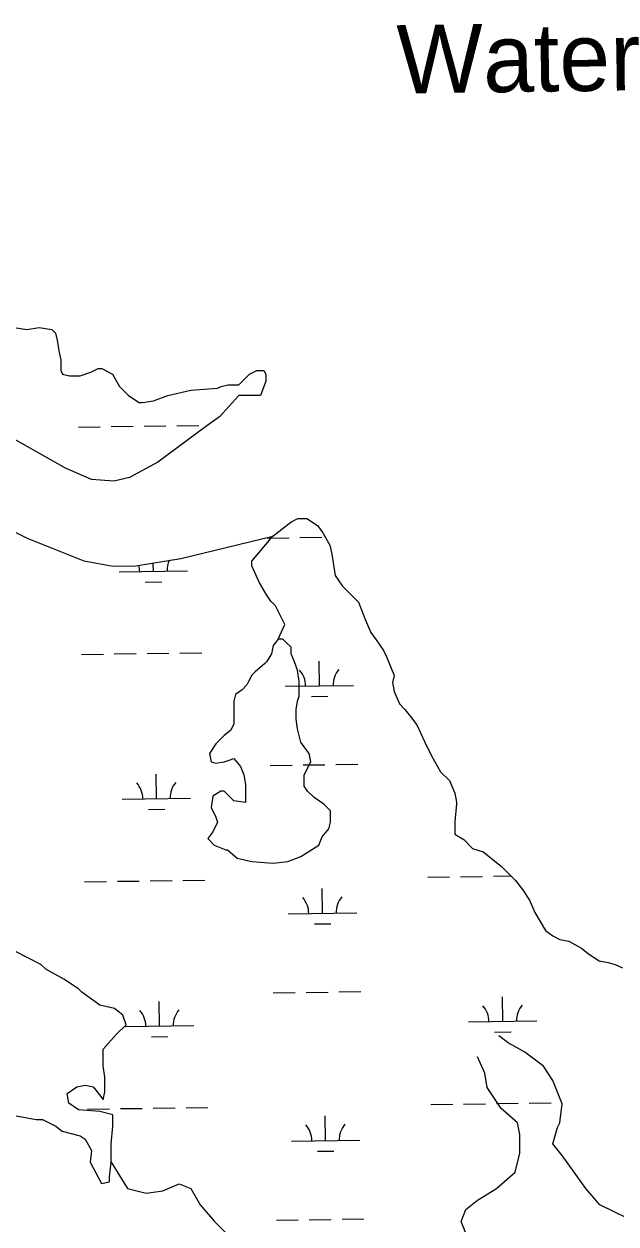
# Model space of a CAD drawing. Extents: x 3753511 to 3791668, y 379550 to 405377.
# Drawn here: x 3781759 to 3782625, y 401064 to 402820 of the extents above; entities that cross this region are included whole.
import ezdxf

# ---------------------------------------------------------------- set-up
doc = ezdxf.new("R2010")
doc.units = 0
for name, color, linetype in [('V-RIVR-IDEN', 7, 'Continuous'), ('V-TOPO-SHOR', 7, 'Continuous'), ('V-WETL-SWMP', 7, 'Continuous')]:
    doc.layers.add(name, color=color, linetype=linetype)

msp = doc.modelspace()

# ---------------------------------------------------------------- linework, layer by layer
at = {"layer": 'V-TOPO-SHOR'}
for p, q in [((3782172.8, 402096.5), (3782188.4, 402086)), ((3782188.4, 402086), (3782196.2, 402075.6)), ((3782196.2, 402075.6), (3782206.7, 402057.3)), ((3782206.7, 402057.3), (3782209.3, 402044.3)), ((3782209.3, 402044.3), (3782214.5, 402013)), ((3782214.5, 402013), (3782224.9, 401997.3)), ((3782224.9, 401997.3), (3782248.4, 401973.8)), ((3782248.4, 401973.8), (3782258.8, 401947.7)), ((3782258.8, 401947.7), (3782266.7, 401929.4)), ((3782266.7, 401929.4), (3782274.5, 401919)), ((3782274.5, 401919), (3782284.9, 401903.4)), ((3782284.9, 401903.4), (3782290.1, 401892.9)), ((3782290.1, 401892.9), (3782300.6, 401866.8)), ((3782300.6, 401866.8), (3782298, 401856.4)), ((3782298, 401856.4), (3782300.6, 401843.3)), ((3782300.6, 401843.3), (3782308.4, 401825.1)), ((3782308.4, 401825.1), (3782316.2, 401817.2)), ((3782316.2, 401817.2), (3782326.6, 401804.2)), ((3782326.6, 401804.2), (3782334.5, 401793.8)), ((3782334.5, 401793.8), (3782344.9, 401770.3)), ((3782344.9, 401770.3), (3782355.3, 401749.4)), ((3782355.3, 401749.4), (3782368.4, 401725.9)), ((3782368.4, 401725.9), (3782381.4, 401712.9)), ((3782381.4, 401712.9), (3782389.2, 401694.6)), ((3782389.2, 401694.6), (3782391.8, 401681.5)), ((3782391.8, 401678.9), (3782389.2, 401652.8)), ((3782391.8, 401681.5), (3782391.8, 401678.9)), ((3782389.2, 401652.8), (3782389.2, 401634.6)), ((3782389.2, 401634.6), (3782402.3, 401626.7)), ((3782402.3, 401626.7), (3782415.3, 401613.7)), ((3782415.3, 401613.7), (3782431, 401608.5)), ((3782431, 401608.5), (3782457, 401587.6)), ((3782457, 401587.6), (3782477.9, 401566.7)), ((3782477.9, 401566.7), (3782488.3, 401553.7)), ((3782488.3, 401553.7), (3782498.8, 401538)), ((3782498.8, 401538), (3782506.6, 401519.8)), ((3782506.6, 401519.8), (3782522.2, 401493.7)), ((3782522.2, 401493.7), (3782532.7, 401485.8)), ((3782532.7, 401485.8), (3782543.1, 401480.6)), ((3782543.1, 401480.6), (3782556.1, 401478)), ((3782556.1, 401478), (3782574.4, 401467.6)), ((3782574.4, 401467.6), (3782584.8, 401459.7)), ((3782584.8, 401459.7), (3782600.5, 401449.3)), ((3782600.5, 401449.3), (3782613.5, 401446.7)), ((3782613.5, 401446.7), (3782623.9, 401444.1)), ((3782623.9, 401444.1), (3782634.4, 401438.9))]:
    msp.add_line(p, q, dxfattribs=at)
for points in [[(3781745.1, 402375.7), (3781763.3, 402373.1), (3781781.6, 402375.7), (3781799.8, 402373.1), (3781805.1, 402367.8), (3781807.7, 402357.4), (3781810.3, 402341.7), (3781812.9, 402328.7), (3781812.9, 402313), (3781815.5, 402307.8), (3781825.9, 402305.2), (3781841.6, 402305.2), (3781857.2, 402310.4), (3781867.6, 402315.7), (3781872.9, 402315.7), (3781888.5, 402307.8), (3781898.9, 402289.6), (3781912, 402276.5), (3781927.6, 402266.1), (3781932.8, 402266.1), (3781948.5, 402268.7), (3781969.4, 402276.5), (3782003.3, 402284.3), (3782042.4, 402286.9), (3782047.6, 402289.6), (3782058, 402292.2), (3782073.7, 402292.2), (3782089.3, 402307.8), (3782099.7, 402313), (3782110.2, 402313), (3782112.8, 402307.8), (3782112.8, 402297.4), (3782105, 402276.5)], [(3782130.8, 401920), (3782140.9, 401941.3), (3782127.1, 401968.8), (3782120.2, 401975.6), (3782113.4, 401985.9), (3782103, 402003.1), (3782092.7, 402027.2), (3782092.7, 402034.1), (3782123.2, 402070.4)], [(3781726.7, 401226.5), (3781776.9, 401217), (3781786.5, 401217), (3781805.6, 401207.4), (3781815.2, 401200.2), (3781841.5, 401193.1), (3781848.7, 401188.3), (3781858.2, 401171.6), (3781855.8, 401154.8), (3781872.6, 401123.7), (3781884.5, 401126.1), (3781884.5, 401133.3), (3781886.9, 401154.8), (3781886.9, 401181.1), (3781889.3, 401207.4), (3781889.3, 401224.2), (3781870.2, 401228.9), (3781839.1, 401231.3), (3781824.8, 401240.9), (3781822.4, 401255.2), (3781836.7, 401264.8), (3781848.7, 401267.2), (3781860.6, 401264.8), (3781870.2, 401252.9), (3781875, 401245.7), (3781877.4, 401257.6), (3781877.4, 401279.2), (3781875, 401295.9), (3781875, 401319.8), (3781894.1, 401341.3), (3781908.5, 401355.7), (3781903.7, 401370), (3781891.7, 401379.6), (3781870.2, 401384.4), (3781843.9, 401403.5), (3781839.1, 401408.3), (3781817.6, 401422.6), (3781791.3, 401437), (3781784.1, 401444.1), (3781745.9, 401463.3)], [(3782642.5, 401072.4), (3782601.5, 401092.1), (3782580.9, 401116.2), (3782563.7, 401140.3), (3782546.5, 401164.3), (3782532.8, 401181.5), (3782539.6, 401205.6), (3782543.1, 401212.5), (3782546.5, 401240), (3782532.8, 401274.3), (3782519, 401295), (3782491.5, 401315.6), (3782467.4, 401329.3), (3782453.7, 401339.7)], [(3782488.7, 400934.2), (3782477.8, 400961.5), (3782477.8, 400968.4), (3782488.1, 400982.1), (3782488.1, 400989), (3782460.6, 400995.9), (3782450.2, 400995.9), (3782436.5, 401006.2), (3782422.7, 401023.4), (3782415.9, 401040.6), (3782405.6, 401050.9), (3782398.7, 401068.1), (3782405.6, 401085.3), (3782422.7, 401099), (3782450.2, 401116.2), (3782477.8, 401140.3), (3782484.6, 401167.8), (3782484.6, 401195.3), (3782481.2, 401212.5), (3782457.1, 401233.1), (3782436.5, 401264), (3782433.1, 401284.7), (3782422.7, 401308.7)], [(3781886.9, 401154.8), (3781910.5, 401116.2), (3781938, 401109.3), (3781962.1, 401112.8), (3781986.2, 401123.1), (3782003.3, 401116.2), (3782017.1, 401092.1), (3782037.7, 401068.1), (3782068.7, 401037.1), (3782085.8, 401033.7), (3782096.2, 401030.3), (3782113.4, 401030.3), (3782137.4, 401023.4), (3782171.8, 401016.5), (3782189, 401019.9), (3782199.3, 401009.6), (3782206.2, 400999.3), (3782213, 400978.7), (3782216.5, 400958.1), (3782226.8, 400937.4), (3782230.2, 400927.1), (3782233.3, 400917.2)]]:
    msp.add_lwpolyline(points, dxfattribs=at)
msp.add_lwpolyline([(3782150, 401898.5), (3782150, 401908), (3782142.8, 401915.2), (3782138, 401920), (3782130.8, 401920), (3782123.7, 401910.4), (3782121.3, 401898.5), (3782114.1, 401886.5), (3782111.7, 401884.1), (3782097.4, 401872.2), (3782092.6, 401867.4), (3782087.8, 401857.8), (3782085.4, 401853), (3782078.2, 401845.9), (3782068.7, 401838.7), (3782066.3, 401829.1), (3782066.3, 401812.4), (3782066.3, 401795.6), (3782061.5, 401786.1), (3782051.9, 401778.9), (3782040, 401766.9), (3782030.4, 401752.6), (3782032.8, 401740.6), (3782040, 401738.3), (3782051.9, 401740.6), (3782059.1, 401743), (3782066.3, 401745.4), (3782075.8, 401733.5), (3782080.6, 401721.5), (3782083, 401707.2), (3782083, 401688), (3782083, 401680.9), (3782066.3, 401683.3), (3782063.9, 401685.6), (3782051.9, 401697.6), (3782047.1, 401697.6), (3782035.2, 401690.4), (3782032.8, 401673.7), (3782040, 401659.3), (3782042.4, 401652.2), (3782035.2, 401637.8), (3782028, 401628.3), (3782037.6, 401618.7), (3782054.3, 401611.5), (3782056.7, 401611.5), (3782071, 401599.6), (3782092.6, 401594.8), (3782123.7, 401592.4), (3782145.2, 401594.8), (3782164.3, 401602), (3782190.6, 401618.7), (3782195.4, 401630.7), (3782205, 401642.6), (3782207.3, 401652.2), (3782207.3, 401668.9), (3782197.8, 401678.5), (3782183.4, 401688), (3782173.9, 401697.6), (3782169.1, 401704.8), (3782169.1, 401721.5), (3782178.6, 401740.6), (3782176.3, 401752.6), (3782169.1, 401762.2), (3782164.3, 401769.3), (3782159.5, 401788.5), (3782157.1, 401802.8), (3782157.1, 401817.2), (3782159.5, 401829.1), (3782161.9, 401836.3), (3782161.9, 401845.9), (3782161.9, 401857.8), (3782159.5, 401874.5), (3782154.7, 401886.5)], close=True, dxfattribs=at)
at = {"layer": 'V-WETL-SWMP'}
for p, q in [((3781838.8, 402230.2), (3781870.8, 402230.7)), ((3781886.8, 402230.9), (3781918.8, 402231.3)), ((3781934.8, 402231.5), (3781966.8, 402232)), ((3781982.8, 402232.2), (3782014.8, 402232.6)), ((3781656.2, 402121.2), (3781764, 402067.6)), ((3782123.2, 402070.4), (3782149.3, 402091.2)), ((3782149.3, 402091.2), (3782159.7, 402096.5)), ((3782159.7, 402096.5), (3782172.8, 402096.5)), ((3782172.8, 402096.5), (3782188.4, 402086)), ((3782188.4, 402086), (3782196.2, 402075.6)), ((3782196.2, 402075.6), (3782206.7, 402057.3)), ((3781764, 402067.6), (3781846.8, 402034.4)), ((3781988.7, 402038.1), (3782123.2, 402070.4)), ((3782114.9, 402067.8), (3782146.9, 402068.2)), ((3782162.9, 402068.4), (3782194.9, 402068.9)), ((3782206.7, 402057.3), (3782209.3, 402044.3)), ((3781922.7, 402027), (3781988.7, 402038.1)), ((3782209.3, 402044.3), (3782214.5, 402013)), ((3781846.8, 402034.4), (3781889.6, 402026.8)), ((3781889.6, 402026.8), (3781922.7, 402027)), ((3781898.5, 402018.4), (3781998.5, 402019.8)), ((3781948.5, 402019.1), (3781948.4, 402031.3)), ((3781936.7, 402003.5), (3781960.7, 402003.8)), ((3782214.5, 402013), (3782224.9, 401997.3)), ((3782224.9, 401997.3), (3782248.4, 401973.8)), ((3782248.4, 401973.8), (3782258.8, 401947.7)), ((3782258.8, 401947.7), (3782266.7, 401929.4)), ((3782266.7, 401929.4), (3782274.5, 401919)), ((3782274.5, 401919), (3782284.9, 401903.4)), ((3781843.3, 401897.6), (3781875.3, 401898)), ((3781891.3, 401898.2), (3781923.3, 401898.7)), ((3781939.3, 401898.9), (3781971.3, 401899.3)), ((3781987.3, 401899.5), (3782019.3, 401900)), ((3782284.9, 401903.4), (3782290.1, 401892.9)), ((3782191.3, 401851.6), (3782190.8, 401887.6)), ((3782290.1, 401892.9), (3782300.6, 401866.8)), ((3782300.6, 401866.8), (3782298, 401856.4)), ((3782141.3, 401850.9), (3782241.3, 401852.2)), ((3782298, 401856.4), (3782300.6, 401843.3)), ((3782300.6, 401843.3), (3782308.4, 401825.1)), ((3782179.5, 401836), (3782203.5, 401836.3)), ((3782308.4, 401825.1), (3782316.2, 401817.2)), ((3782316.2, 401817.2), (3782326.6, 401804.2)), ((3782326.6, 401804.2), (3782334.5, 401793.8)), ((3782334.5, 401793.8), (3782344.9, 401770.3)), ((3782344.9, 401770.3), (3782355.3, 401749.4)), ((3782215.4, 401736.4), (3782247.4, 401736.9)), ((3782355.3, 401749.4), (3782368.4, 401725.9)), ((3781953, 401686.5), (3781952.5, 401722.5)), ((3782119.4, 401735.1), (3782151.4, 401735.6)), ((3782167.4, 401735.8), (3782199.4, 401736.2)), ((3782368.4, 401725.9), (3782381.4, 401712.9)), ((3782381.4, 401712.9), (3782389.2, 401694.6)), ((3781903, 401685.8), (3782003, 401687.1)), ((3782389.2, 401694.6), (3782391.8, 401681.5)), ((3781941.2, 401670.9), (3781965.2, 401671.2)), ((3782391.8, 401678.9), (3782389.2, 401652.8)), ((3782391.8, 401681.5), (3782391.8, 401678.9)), ((3782389.2, 401652.8), (3782389.2, 401634.6)), ((3782389.2, 401634.6), (3782402.3, 401626.7)), ((3782402.3, 401626.7), (3782415.3, 401613.7)), ((3782415.3, 401613.7), (3782431, 401608.5)), ((3782431, 401608.5), (3782457, 401587.6)), ((3782457, 401587.6), (3782477.9, 401566.7)), ((3781847.8, 401565), (3781879.8, 401565.4)), ((3781895.8, 401565.6), (3781927.8, 401566)), ((3781943.8, 401566.3), (3781975.8, 401566.7)), ((3781991.8, 401566.9), (3782023.8, 401567.3)), ((3782349.7, 401571.7), (3782381.7, 401572.2)), ((3782397.7, 401572.4), (3782429.7, 401572.8)), ((3782445.7, 401573), (3782471.2, 401573.4)), ((3782477.9, 401566.7), (3782488.3, 401553.7)), ((3782195.8, 401518.9), (3782195.3, 401554.9)), ((3782488.3, 401553.7), (3782498.8, 401538)), ((3782498.8, 401538), (3782506.6, 401519.8)), ((3782145.8, 401518.2), (3782245.8, 401519.6)), ((3782506.6, 401519.8), (3782522.2, 401493.7)), ((3782184, 401503.3), (3782208, 401503.6)), ((3782522.2, 401493.7), (3782532.7, 401485.8)), ((3782532.7, 401485.8), (3782543.1, 401480.6)), ((3782543.1, 401480.6), (3782556.1, 401478)), ((3782556.1, 401478), (3782574.4, 401467.6)), ((3782574.4, 401467.6), (3782584.8, 401459.7)), ((3782584.8, 401459.7), (3782600.5, 401449.3)), ((3782600.5, 401449.3), (3782613.5, 401446.7)), ((3782613.5, 401446.7), (3782623.9, 401444.1)), ((3782623.9, 401444.1), (3782634.4, 401438.9)), ((3782171.9, 401403.1), (3782203.9, 401403.6)), ((3782219.9, 401403.8), (3782251.9, 401404.2)), ((3781957.5, 401353.8), (3781957, 401389.8)), ((3782123.9, 401402.5), (3782155.9, 401402.9)), ((3782459.4, 401360.6), (3782458.9, 401396.6)), ((3781907.5, 401353.1), (3782007.5, 401354.5)), ((3782409.4, 401359.9), (3782509.4, 401361.3)), ((3781945.7, 401338.2), (3781969.7, 401338.5)), ((3782447.6, 401345), (3782471.6, 401345.3)), ((3781852.3, 401232.3), (3781884.3, 401232.7)), ((3781900.3, 401233), (3781932.3, 401233.4)), ((3781948.3, 401233.6), (3781980.3, 401234)), ((3781996.3, 401234.3), (3782028.3, 401234.7)), ((3782354.2, 401239.1), (3782386.2, 401239.5)), ((3782402.2, 401239.7), (3782434.2, 401240.2)), ((3782450.2, 401240.4), (3782482.2, 401240.8)), ((3782498.1, 401241), (3782530.1, 401241.5)), ((3782200.3, 401186.3), (3782199.8, 401222.3)), ((3782150.3, 401185.6), (3782250.3, 401186.9)), ((3782188.5, 401170.7), (3782212.5, 401171)), ((3782128.4, 401069.9), (3782160.4, 401070.3)), ((3782176.4, 401070.5), (3782208.4, 401070.9)), ((3782224.4, 401071.2), (3782256.4, 401071.6))]:
    msp.add_line(p, q, dxfattribs=at)
msp.add_lwpolyline([(3781745.1, 402375.7), (3781763.3, 402373.1), (3781781.6, 402375.7), (3781799.8, 402373.1), (3781805.1, 402367.8), (3781807.7, 402357.4), (3781810.3, 402341.7), (3781812.9, 402328.7), (3781812.9, 402313), (3781815.5, 402307.8), (3781825.9, 402305.2), (3781841.6, 402305.2), (3781857.2, 402310.4), (3781867.6, 402315.7), (3781872.9, 402315.7), (3781888.5, 402307.8), (3781898.9, 402289.6), (3781912, 402276.5), (3781927.6, 402266.1), (3781932.8, 402266.1), (3781948.5, 402268.7), (3781969.4, 402276.5), (3782003.3, 402284.3), (3782042.4, 402286.9), (3782047.6, 402289.6), (3782058, 402292.2), (3782073.7, 402292.2), (3782089.3, 402307.8), (3782099.7, 402313), (3782110.2, 402313), (3782112.8, 402307.8), (3782112.8, 402297.4), (3782105, 402276.5), (3782073.7, 402276.5), (3782045, 402245.2), (3782026.7, 402232.1), (3781954.9, 402178.6), (3781913.5, 402156.5), (3781890.7, 402150.9), (3781858.2, 402153.7), (3781819.8, 402170.1), (3781744.7, 402212.6)], dxfattribs=at)
for centre, start, end in [((3782003.7, 402020.3), 154.9046, 181.5465), ((3781893.3, 402018.8), 0.0029, 14.7021), ((3782136, 401851.3), 0.0029, 41.5465), ((3782246.5, 401852.8), 140.0029, 181.5465), ((3781897.8, 401686.2), 0.0029, 41.5465), ((3782008.2, 401687.7), 140.0029, 181.5465), ((3782140.5, 401518.6), 0.0029, 41.5465), ((3782251, 401520.1), 140.0029, 181.5465), ((3781902.3, 401353.5), 0.0029, 41.5465), ((3782012.7, 401355), 140.0029, 181.5465), ((3782404.1, 401360.3), 0.0029, 41.5465), ((3782514.6, 401361.8), 140.0029, 181.5465), ((3782255.5, 401187.5), 140.0029, 181.5465), ((3782145, 401186), 0.0029, 41.5465)]:
    msp.add_arc(centre, 35.2, start, end, dxfattribs=at)

# ---------------------------------------------------------------- texts
at = {"layer": 'V-RIVR-IDEN'}
msp.add_text('Water', height=100, rotation=0.791, dxfattribs=at).set_placement((3782305, 402718.1))

doc.saveas('drawing.dxf')
